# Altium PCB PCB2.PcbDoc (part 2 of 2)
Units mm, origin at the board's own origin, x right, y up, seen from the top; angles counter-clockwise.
Board outline 165.1 x 160.02 mm, 2 copper layers (Top Layer, Bottom Layer); 328 components, 756 nets, 2625 pads, 0 vias.
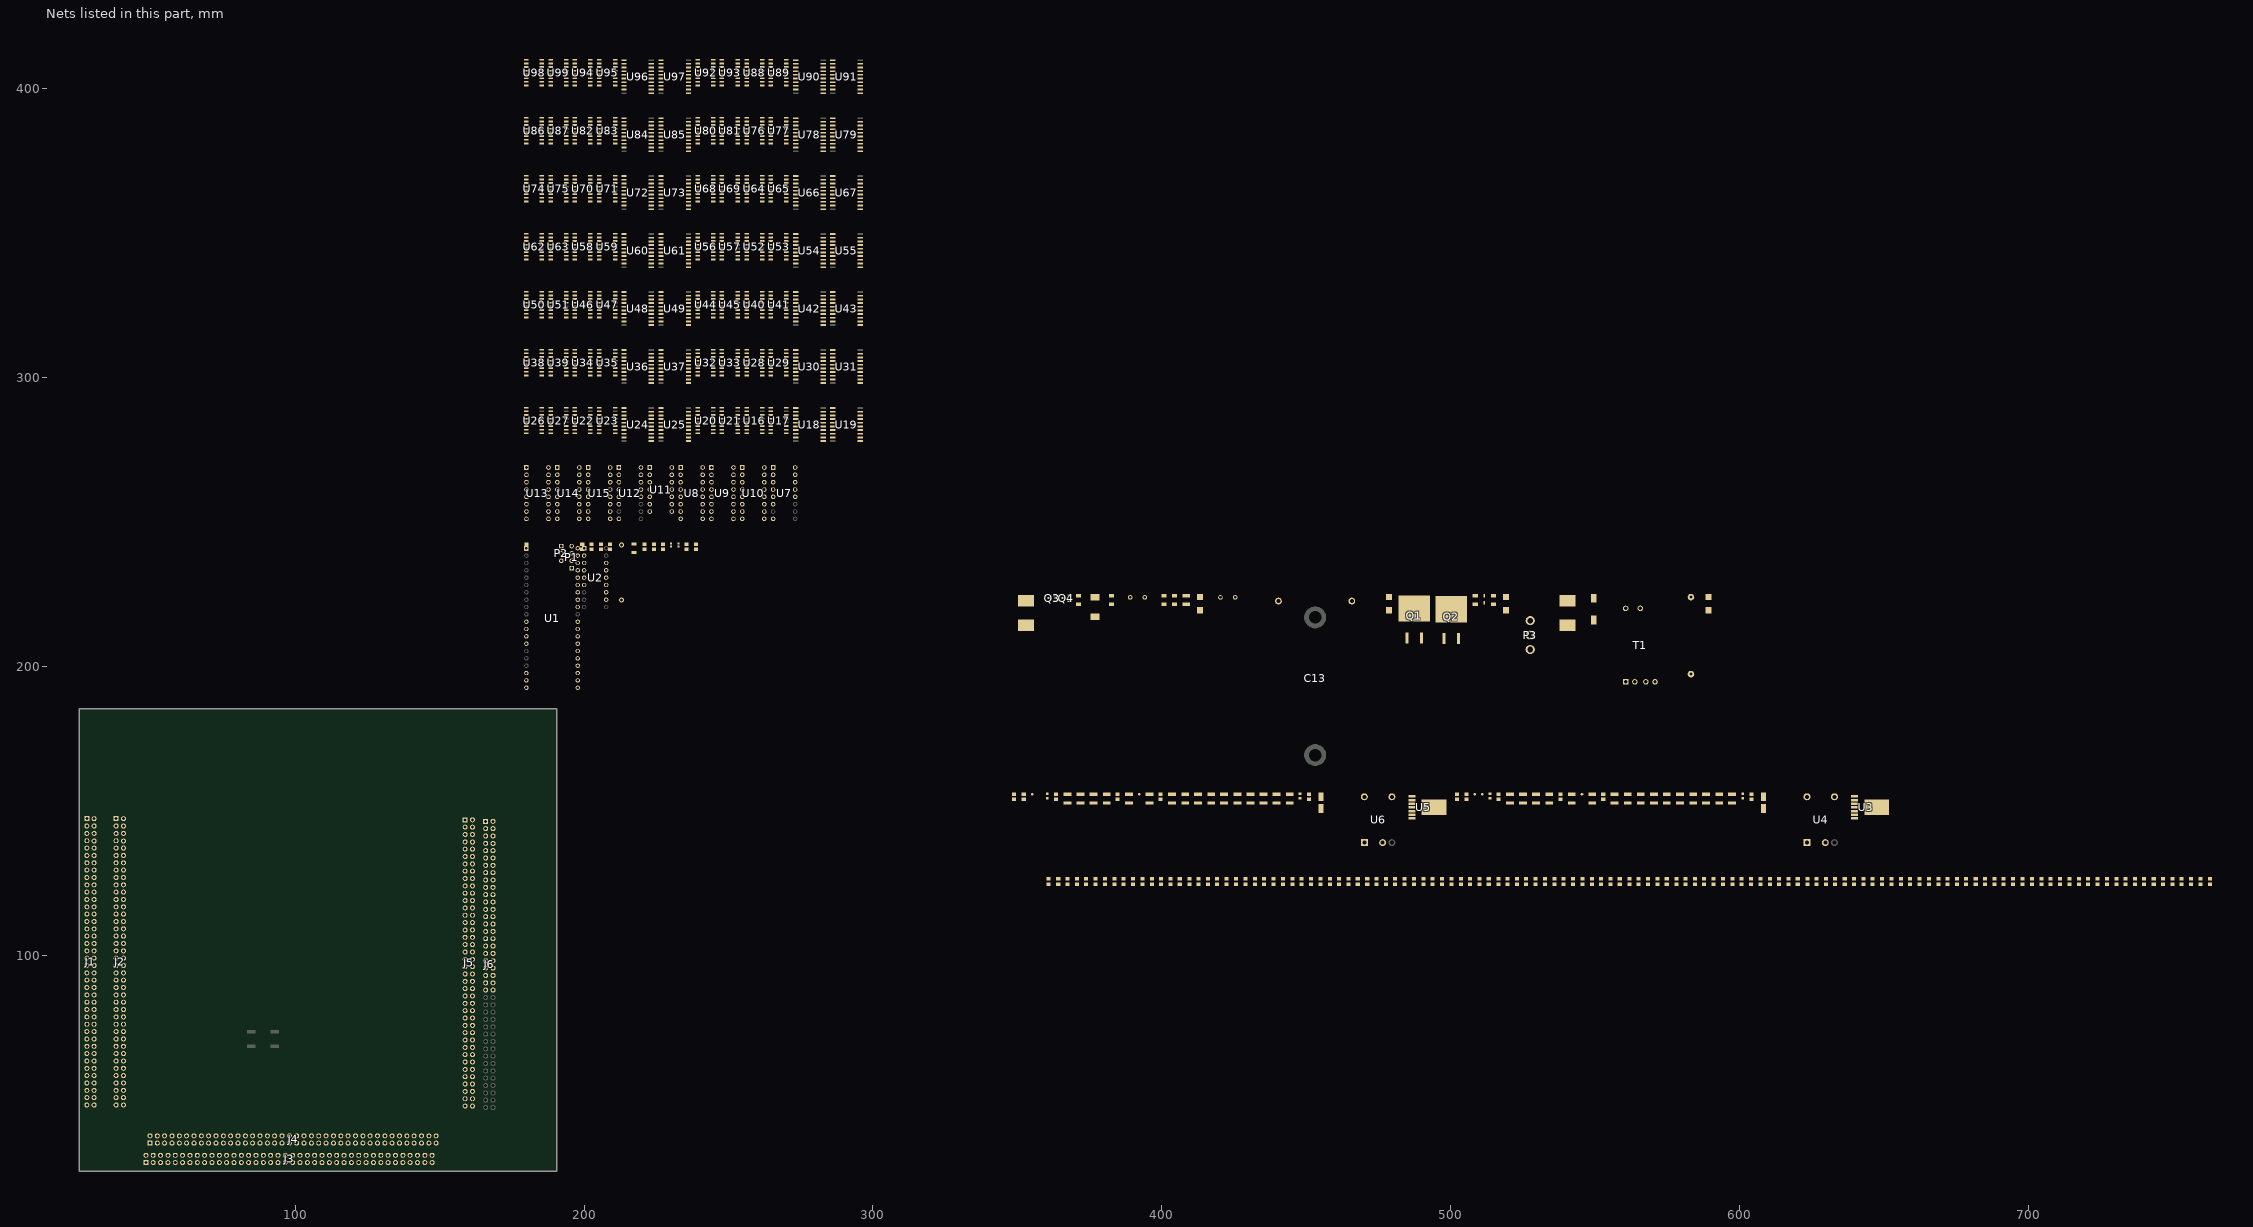
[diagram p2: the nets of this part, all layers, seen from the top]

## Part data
C1 C5 C6 C7 C8 C9 C10 C11 C52 C53 C54 C55 C56 C57 C58 C59 C60 C61 C62 C63 C64 C65 C66 C67 C68 C69 C70 C71 C72 C73 C74 C75 C76 C77 C78 C79 C80 C81 C82 C83 C84 C85 C86 C87 C88 C89 C90 C91 C92 C93 C94 C95 C96 C97 C98 C99 C100 C101 C102 C103 C104 C105 C106 C107 C108 C109 C110 C111 C112 C113 C114 C115 C116 C117 C118 C119 C120 C121 C122 C123 C124 C125 C126 C127 C128 C129 C130 C131 C132 C133 C134 C135 C136 C137 C138 C139 C140 C141 C142 C143 C144 C145 C146 C147 C148 C149 C150 C151 C152 C153 C154 C155 C156 C157 C158 C159 C160 C161 C162 C163 C164 C165 C166 C167 C168 C169 C170 C171 C172 C173 C174 C175 C176: "CAPACITOR, CERAMIC, 0.1UF, 10%, X7R, 50V, 0805"
C2 C3: "CAP CERAMIC 22PF 25V 10% COG 0402"
C4: "CAPACITOR, CERAMIC, 0.47UF 10%, X7R, 50V, 0805"
C12 C15: "CAPACITOR, ALUM ELECT, 470UF, 50V, 477-50V-20AV, -55C TO 105 C"
C13: library part MLPCAPSHORT.1
C14: "CAPACITOR, CERAMIC, 1.0UF 10%, X7R, 100V, 2.7mm"
C16 C17 C18 C19 C27 C28 C34 C35 C36 C37 C45 C46: "CAPACITOR, CERAMIC, 4.7UF 10%, X7R, 50V, 1210"
C20 C21 C22 C23 C24 C25 C29 C30 C31 C32 C38 C39 C40 C41 C42 C43 C47 C48 C49 C50: "CAPACITOR, CERAMIC, 22UF 10%, X7R, 25V, 1210"
C26 C44: "CAPACITOR, CERAMIC, 0.033UF 10%, X7R, 50V, 0805"
C33 C51: "CAPACITOR, CERAMIC, 4700PF 10%, X7R, 100V"
CR1: library part 1206_LED_GRN, "LED, GRN, SMT"
CR2 CR3 CR4 CR5: "DIODE, RECTIFIER, 200V, 2 AMP, SMA PACKAGE"
CR6: "DIODE, ZENER, 36V, DO214AB+"
F1: library part FUSE_1A_A, "FUSE, AXIAL LEADED, 1A, 500VAC"
J1 J2 J3 J4 J5 J6: "HEADER, 80 PIN"
L1: "INDUCTOR, BEAD, SMT, 25-300MHz (43 material)"
L2 L3: library part 1489-BF33U_X, "INDUCTOR, PWR, MSS1260"
L4 L5: "INDUCTOR, BEAD, SMT, < 50 MHz (73 material)"
P1: "HEADER, 4 PIN, ST, 0.100 CTRS"
P2: "HEADER, 3 PIN, RA, 0.100 CTRS"
P3: "HEADER, 3 PIN, ST, 5mm CTRS"
Q1: "POWER MOSFET, P-CHANNEL, 100V, 33A, D2PAK"
Q2: "POWER MOSFET, P-CHANNEL, 60V, 27A, D2PAK"
Q3 Q4: library part FMMTA42.1
R1 R11 R17: "RESISTOR, 10K OHM, 1%, 100 PPM, 0805"
R2: "RESISTOR, 56 OHMS, 1%, 20PPM, SILICONE-CERAMIC WIREWOUND"
R3 R6 R7: "RESISTOR, 20K, 1%, 100 PPM, 1206"
R4: "Resistor, General Purpose, 47.5K, 1%, 100 PPM, 1206"
R5: "RESISTOR, THIN FILM 47.5K, 0.1%, 100 PPM, 1206"
R8: "RESISTOR, 10K, 1%, 100 PPM, 1206"
R9 R15: "RESISTOR, 249K OHMS, 1%, 0805"
R10 R16: "RESISTOR, 26.7K OHM, 1%, 100 PPM, 0603"
R12 R18: "RESISTOR, 15K, 1%, 100 PPM, 0805"
R13 R19: "RESISTOR, 1.500K OHM, 5%, 200 PPM, 0603"
R14 R20: "RESISTOR, 1K, 1%, 100 PPM, 0805"
T1: "TRANSFORMER, 400V, 400HZ"
TP14 TP15 TP16 TP22 TP24: library part TP35, "TEST POINT, 0.035 dia Oct pad w/ 0.010 hole, or SMT"
U1: "High Performance, Enhanced Flash, USB Microcontroller with nanoWatt Technology, 32K Flash, 40-Pin PDIP, Industrial Temperature Range"
U2: "3.0V TO 5.5V, Low-Power, up to 1Mbps, True RS-232 Transceiver Using Four 0.1µF External Capacitor"
U3 U5: "3A POWER MODULE, 42V MAX"
U4 U6: "MODULE, 11.85V - 22V SWITCHING REGULATOR (1.5A)"
U7 U8 U9 U10 U12 U13 U14 U15: "3-to-8 Line Decoder Inverting"
U11: "IC, CMOS HEX INVERTER , DIP14"
U16 U17 U20 U21 U22 U23 U26 U27 U28 U29 U32 U33 U34 U35 U38 U39 U40 U41 U44 U45 U46 U47 U50 U51 U52 U53 U56 U57 U58 U59 U62 U63 U64 U65 U68 U69 U70 U71 U74 U75 U76 U77 U80 U81 U82 U83 U86 U87 U88 U89 U92 U93 U94 U95 U98 U99: library part ADG439FBR_X, "IC, 8 channel,  Fault-Protected Analog Multiplexers"
U18 U19 U24 U25 U30 U31 U36 U37 U42 U43 U48 U49 U54 U55 U60 U61 U66 U67 U72 U73 U78 U79 U84 U85 U90 U91 U96 U97: "IC, LATCH, OCTAL TRANSPARENT, TRISTATE"
VR1: library part BZT52CXXX.1

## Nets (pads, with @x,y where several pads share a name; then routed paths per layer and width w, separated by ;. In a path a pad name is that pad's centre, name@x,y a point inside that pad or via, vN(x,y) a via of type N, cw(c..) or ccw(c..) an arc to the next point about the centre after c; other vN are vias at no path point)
28V0: L4.1 L5.1
28VDC: C12.1 L2.2 Q1.4
+5V0: C5.2 C6.2 C8.2 C36.1 C37.1 C38.1 C39.1 C40.1 C44.1 C46.1 C47.1 C48.1 C52.1 C53.1 C54.1 C55.1 C56.1 C57.1 C58.1 C59.1 C60.1 C61.1 C62.1 C63.1 C64.1 C65.1 C66.1 C67.1 C68.1 C69.1 C70.1 C71.1 C72.1 C73.1 C74.1 C75.1 C76.1 C77.1 C78.1 C79.1 C80.1 C81.1 C82.1 C83.1 C84.1 C85.1 C86.1 C87.1 C88.1 C89.1 C90.1 C91.1 C92.1 C93.1 C94.1 C95.1 C96.1 C105.1 C106.1 C107.1 C108.1 C109.1 C110.1 C111.1 C112.1 C137.1 C138.1 C139.1 C140.1 C141.1 C142.1 C143.1 C144.1 C145.1 C146.1 C147.1 C148.1 C149.1 C150.1 C151.1 C152.1 C153.1 C154.1 C155.1 C156.1 C157.1 C158.1 C159.1 C160.1 R1.2 R16.2 U1.11 U1.32 U2.16 U5.7 U6.2 U7.16 U8.16 U9.16 U10.16 U11.14 U12.16 U13.16 U14.16 U15.16 U16.13 U17.4 U20.4 U21.4 U22.4 U23.4 U26.4 U27.4 U28.13 U29.13 U32.13 U33.13 U34.13 U35.13 U38.13 U39.13 U40.13 U41.13 U44.13 U45.13 U46.13 U47.13 U50.13 U51.13 U52.13 U53.13 U56.13 U57.13 U58.13 U59.13 U62.13 U63.13 U64.13 U65.13 U68.13 U69.13 U70.13 U71.13 U74.13 U75.13 U76.13 U77.13 U80.13 U81.13 U82.13 U83.13 U86.13 U87.13 U88.13 U89.13 U92.13 U93.13 U94.13 U95.13 U98.13 U99.13
+5V_USB: P1.1
+15V0: C18.1 C19.1 C20.1 C21.1 C22.1 C26.1 C28.1 C29.1 C30.1 R10.2 U3.7 U4.2
+DCOR: C13.1 Q1.3 Q2.3 R3.2 R4.2
-5V0: C41.1 C42.1 C43.1 C49.1 C50.1 C97.1 C98.1 C99.1 C100.1 C101.1 C102.1 C103.1 C104.1 C113.1 C114.1 C115.1 C116.1 C117.1 C118.1 C119.1 C120.1 C121.1 C122.1 C123.1 C124.1 C125.1 C126.1 C127.1 C128.1 C129.1 C130.1 C131.1 C132.1 C133.1 C134.1 C135.1 C136.1 C161.1 C162.1 C163.1 C164.1 C165.1 C166.1 C167.1 C168.1 C169.1 C170.1 C171.1 C172.1 C173.1 C174.1 C175.1 C176.1 U6.1 U6.5 U17.13 U20.13 U21.13 U22.13 U23.13 U26.13 U27.13 U28.4 U29.4 U32.4 U33.4 U34.4 U35.4 U38.4 U39.4 U40.4 U41.4 U44.4 U45.4 U46.4 U47.4 U50.4 U51.4 U52.4 U53.4 U56.4 U57.4 U58.4 U59.4 U62.4 U63.4 U64.4 U65.4 U68.4 U69.4 U70.4 U71.4 U74.4 U75.4 U76.4 U77.4 U80.4 U81.4 U82.4 U83.4 U86.4 U87.4 U88.4 U89.4 U92.4 U93.4 U94.4 U95.4 U98.4 U99.4
-15V0: C23.1 C24.1 C25.1 C31.1 C32.1 U4.1 U4.5
BJTB1: Q3.1 Q4.3 R4.1
BJTB2: Q4.1 R5.1 R8.2
BJTC1: Q3.3 R6.1
D0: U1.33 U18.3 U19.3 U24.3 U25.3 U30.3 U31.3 U36.3 U37.3 U42.3 U43.3 U48.3 U49.3 U54.3 U55.3 U60.3 U61.3 U66.3 U67.3 U72.3 U73.3 U78.3 U79.3 U84.3 U85.3 U90.3 U91.3 U96.3 U97.3
D1: U1.34 U18.4 U19.4 U24.4 U25.4 U30.4 U31.4 U36.4 U37.4 U42.4 U43.4 U48.4 U49.4 U54.4 U55.4 U60.4 U61.4 U66.4 U67.4 U72.4 U73.4 U78.4 U79.4 U84.4 U85.4 U90.4 U91.4 U96.4 U97.4
D2: U1.35 U18.7 U19.7 U24.7 U25.7 U30.7 U31.7 U36.7 U37.7 U42.7 U43.7 U48.7 U49.7 U54.7 U55.7 U60.7 U61.7 U66.7 U67.7 U72.7 U73.7 U78.7 U79.7 U84.7 U85.7 U90.7 U91.7 U96.7 U97.7
D3: U1.36 U18.8 U19.8 U24.8 U25.8 U30.8 U31.8 U36.8 U37.8 U42.8 U43.8 U48.8 U49.8 U54.8 U55.8 U60.8 U61.8 U66.8 U67.8 U72.8 U73.8 U78.8 U79.8 U84.8 U85.8 U90.8 U91.8 U96.8 U97.8
D4: U1.37 U18.13 U19.13 U24.13 U25.13 U30.13 U31.13 U36.13 U37.13 U42.13 U43.13 U48.13 U49.13 U54.13 U55.13 U60.13 U61.13 U66.13 U67.13 U72.13 U73.13 U78.13 U79.13 U84.13 U85.13 U90.13 U91.13 U96.13 U97.13
D5: U1.38 U18.14 U19.14 U24.14 U25.14 U30.14 U31.14 U36.14 U37.14 U42.14 U43.14 U48.14 U49.14 U54.14 U55.14 U60.14 U61.14 U66.14 U67.14 U72.14 U73.14 U78.14 U79.14 U84.14 U85.14 U90.14 U91.14 U96.14 U97.14
D6: U1.39 U18.17 U19.17 U24.17 U25.17 U30.17 U31.17 U36.17 U37.17 U42.17 U43.17 U48.17 U49.17 U54.17 U55.17 U60.17 U61.17 U66.17 U67.17 U72.17 U73.17 U78.17 U79.17 U84.17 U85.17 U90.17 U91.17 U96.17 U97.17
D7: U1.40 U18.18 U19.18 U24.18 U25.18 U30.18 U31.18 U36.18 U37.18 U42.18 U43.18 U48.18 U49.18 U54.18 U55.18 U60.18 U61.18 U66.18 U67.18 U72.18 U73.18 U78.18 U79.18 U84.18 U85.18 U90.18 U91.18 U96.18 U97.18
D+: P1.2 U1.24
D-: P1.3 U1.23
DGND: C12.2 C13.2 C16.2 C17.2 C18.2 C19.2 C20.2 C21.2 C22.2 C23.2 C24.2 C25.2 C27.2 C28.2 C29.2 C30.2 C31.2 C32.2 C33.2 C34.2 C35.2 C36.2 C37.2 C38.2 C39.2 C40.2 C41.2 C42.2 C43.2 C45.2 C46.2 C47.2 C48.2 C49.2 C50.2 C51.2 L3.2 Q3.2 Q4.2 R7.1 R8.1 R12.1 R13.1 R14.1 R18.1 R19.1 R20.1 U3.4 U3.8 U5.4 U5.8
DLE1: U1.27 U7.4 U9.4 U10.4 U11.1 U12.6 U13.6 U14.6 U15.6
DLE2: U1.28 U7.6 U8.4 U9.5 U10.6 U11.9 U11.11 U13.4 U14.4
DLE3: U1.29 U8.5 U9.6 U10.5 U11.3 U11.5 U11.13 U13.5 U15.5
GND: C1.1 C2.1 C3.1 C4.1 C5.1 C6.1 C8.1 C9.1 C11.1 C52.2 C53.2 C54.2 C55.2 C56.2 C57.2 C58.2 C59.2 C60.2 C61.2 C62.2 C63.2 C64.2 C65.2 C66.2 C67.2 C68.2 C69.2 C70.2 C71.2 C72.2 C73.2 C74.2 C75.2 C76.2 C77.2 C78.2 C79.2 C80.2 C81.2 C82.2 C83.2 C84.2 C85.2 C86.2 C87.2 C88.2 C89.2 C90.2 C91.2 C92.2 C93.2 C94.2 C95.2 C96.2 C97.2 C98.2 C99.2 C100.2 C101.2 C102.2 C103.2 C104.2 C105.2 C106.2 C107.2 C108.2 C109.2 C110.2 C111.2 C112.2 C113.2 C114.2 C115.2 C116.2 C117.2 C118.2 C119.2 C120.2 C121.2 C122.2 C123.2 C124.2 C125.2 C126.2 C127.2 C128.2 C129.2 C130.2 C131.2 C132.2 C133.2 C134.2 C135.2 C136.2 C137.2 C138.2 C139.2 C140.2 C141.2 C142.2 C143.2 C144.2 C145.2 C146.2 C147.2 C148.2 C149.2 C150.2 C151.2 C152.2 C153.2 C154.2 C155.2 C156.2 C157.2 C158.2 C159.2 C160.2 C161.2 C162.2 C163.2 C164.2 C165.2 C166.2 C167.2 C168.2 C169.2 C170.2 C171.2 C172.2 C173.2 C174.2 C175.2 C176.2 P1.4 P2.1 P3.3 R2.1 U1.12 U1.31 U2.15 U7.8 U8.8 U9.8 U10.8 U11.7 U12.8 U13.8 U14.8 U15.8 U16.5 U17.5 U20.5 U21.5 U22.5 U23.5 U26.5 U27.5 U28.5 U29.5 U32.5 U33.5 U34.5 U35.5 U38.5 U39.5 U40.5 U41.5 U44.5 U45.5 U46.5 U47.5 U50.5 U51.5 U52.5 U53.5 U56.5 U57.5 U58.5 U59.5 U62.5 U63.5 U64.5 U65.5 U68.5 U69.5 U70.5 U71.5 U74.5 U75.5 U76.5 U77.5 U80.5 U81.5 U82.5 U83.5 U86.5 U87.5 U88.5 U89.5 U92.5 U93.5 U94.5 U95.5 U98.5 U99.5
LE1: U8.15 U18.11
LE2: U8.14 U24.11
LE3: U8.13 U19.11
LE4: U8.12 U25.11
LE5: U8.11 U30.11
LE6: U8.10 U36.11
LE7: U8.9 U31.11
LE8: U8.7 U37.11
LE9: U9.15 U42.11
LE10: U9.14 U48.11
LE11: U9.13 U43.11
LE12: U9.12 U49.11
LE13: U9.11 U54.11
LE14: U9.10 U60.11
LE15: U9.9 U55.11
LE16: U9.7 U61.11
LE17: U10.15 U66.11
LE18: U10.14 U72.11
LE19: U10.13 U67.11
LE20: U10.12 U73.11
LE21: U10.11 U78.11
LE22: U10.10 U84.11
LE23: U10.9 U79.11
LE24: U10.7 U85.11
LE25: U7.15 U90.11
LE26: U7.14 U96.11
LE27: U7.13 U91.11
LE28: U7.12 U97.11
LOE1: U13.15 U18.1
LOE2: U13.14 U24.1
LOE3: U13.13 U19.1
LOE4: U13.12 U25.1
LOE5: U13.11 U30.1
LOE6: U13.10 U36.1
LOE7: U13.9 U31.1
LOE8: U13.7 U37.1
LOE9: U14.15 U42.1
LOE10: U14.14 U48.1
LOE11: U14.13 U43.1
LOE12: U14.12 U49.1
LOE13: U14.11 U54.1
LOE14: U14.10 U60.1
LOE15: U14.9 U55.1
LOE16: U14.7 U61.1
LOE17: U15.15 U66.1
LOE18: U15.14 U72.1
LOE19: U15.13 U67.1
LOE20: U15.12 U73.1
LOE21: U15.11 U78.1
LOE22: U15.10 U84.1
LOE23: U15.9 U79.1
LOE24: U15.7 U85.1
LOE25: U12.15 U90.1
LOE26: U12.14 U96.1
LOE27: U12.13 U91.1
LOE28: U12.12 U97.1
MOSFEED1: Q2.1 R3.1 R6.2
NetC1_2: C1.2 R1.1 U1.1
NetC2_2: C2.2 U1.13
NetC3_2: C3.2 U1.14
NetC4_2: C4.2 U1.18
NetC7_1: C7.1 U2.3
NetC7_2: C7.2 U2.1
NetC9_2: C9.2 U2.2
NetC10_1: C10.1 U2.5
NetC10_2: C10.2 U2.4
NetC11_2: C11.2 U2.6
NetC14_1: C14.1 C15.1 CR3.1 CR4.1 CR6.1 L2.1
NetC14_2: C14.2 C15.2 CR2.2 CR5.2 CR6.2 L3.1
NetC16_1: C16.1 C17.1 C27.1 L4.2 R9.1 R11.2 U3.1
NetC26_2: C26.2 R10.1 R13.2 TP14.1 U3.6
NetC33_1: C33.1 TP16.1 U3.5
NetC34_1: C34.1 C35.1 C45.1 L5.2 R15.1 R17.2 U5.1
NetC44_2: C44.2 R16.1 R19.2 TP22.1 U5.6
NetC51_1: C51.1 TP24.1 U5.5
NetCR1_1: CR1.1 R2.2
NetCR1_2: CR1.2 U1.19
NetCR2_1: CR2.1 CR3.2 T1.5
NetCR4_2: CR4.2 CR5.1 T1.6
NetF1_1: F1.1 P3.1
NetF1_2: F1.2 L1.1
NetL1_2: L1.2 T1.1
NetP3_2: P3.2 T1.4
NetQ1_1: Q1.1 R7.2
NetR9_2: R9.2 U3.2
NetR11_1: R11.1 R14.2 TP15.1 U3.3
NetR12_2: R12.2 U4.4
NetR15_2: R15.2 U5.2
NetR17_1: R17.1 R20.2 U5.3
NetR18_2: R18.2 U6.4
NetT1_2: T1.2 T1.3
NetU7_5: U7.5 U11.4
NetU8_6: U8.6 U11.2
NetU11_6: U11.6 U14.5
NetU11_8: U11.8 U12.4
NetU11_10: U11.10 U15.4
NetU11_12: U11.12 U12.5
NetU16_1: U16.1 U18.2
NetU16_8: U16.8 U18.5
NetU16_9: U16.9 U18.6
NetU16_16: U16.16 U18.9
NetU17_1: U17.1 U19.2
NetU17_8: U17.8 U19.5
NetU17_9: U17.9 U19.6
NetU17_16: U17.16 U19.9
NetU18_12: U18.12 U20.1
NetU18_15: U18.15 U20.8
NetU18_16: U18.16 U20.9
NetU18_19: U18.19 U20.16
NetU19_12: U19.12 U21.1
NetU19_15: U19.15 U21.8
NetU19_16: U19.16 U21.9
NetU19_19: U19.19 U21.16
NetU22_1: U22.1 U24.2
NetU22_8: U22.8 U24.5
NetU22_9: U22.9 U24.6
NetU22_16: U22.16 U24.9
NetU23_1: U23.1 U25.2
NetU23_8: U23.8 U25.5
NetU23_9: U23.9 U25.6
NetU23_16: U23.16 U25.9
NetU24_12: U24.12 U26.1
NetU24_15: U24.15 U26.8
NetU24_16: U24.16 U26.9
NetU24_19: U24.19 U26.16
NetU25_12: U25.12 U27.1
NetU25_15: U25.15 U27.8
NetU25_16: U25.16 U27.9
NetU25_19: U25.19 U27.16
NetU28_1: U28.1 U30.2
NetU28_8: U28.8 U30.9
NetU28_9: U28.9 U30.6
NetU28_16: U28.16 U30.5
NetU29_1: U29.1 U31.2
NetU29_8: U29.8 U31.9
NetU29_9: U29.9 U31.6
NetU29_16: U29.16 U31.5
NetU30_12: U30.12 U32.1
NetU30_15: U30.15 U32.16
NetU30_16: U30.16 U32.9
NetU30_19: U30.19 U32.8
NetU31_12: U31.12 U33.1
NetU31_15: U31.15 U33.16
NetU31_16: U31.16 U33.9
NetU31_19: U31.19 U33.8
NetU34_1: U34.1 U36.2
NetU34_8: U34.8 U36.9
NetU34_9: U34.9 U36.6
NetU34_16: U34.16 U36.5
NetU35_1: U35.1 U37.2
NetU35_8: U35.8 U37.9
NetU35_9: U35.9 U37.6
NetU35_16: U35.16 U37.5
NetU36_12: U36.12 U38.1
NetU36_15: U36.15 U38.16
NetU36_16: U36.16 U38.9
NetU36_19: U36.19 U38.8
NetU37_12: U37.12 U39.1
NetU37_15: U37.15 U39.16
NetU37_16: U37.16 U39.9
NetU37_19: U37.19 U39.8
NetU40_1: U40.1 U42.2
NetU40_8: U40.8 U42.9
NetU40_9: U40.9 U42.6
NetU40_16: U40.16 U42.5
NetU41_1: U41.1 U43.2
NetU41_8: U41.8 U43.9
NetU41_9: U41.9 U43.6
NetU41_16: U41.16 U43.5
NetU42_12: U42.12 U44.1
NetU42_15: U42.15 U44.16
NetU42_16: U42.16 U44.9
NetU42_19: U42.19 U44.8
NetU43_12: U43.12 U45.1
NetU43_15: U43.15 U45.16
NetU43_16: U43.16 U45.9
NetU43_19: U43.19 U45.8
NetU46_1: U46.1 U48.2
NetU46_8: U46.8 U48.9
NetU46_9: U46.9 U48.6
NetU46_16: U46.16 U48.5
NetU47_1: U47.1 U49.2
NetU47_8: U47.8 U49.9
NetU47_9: U47.9 U49.6
NetU47_16: U47.16 U49.5
NetU48_12: U48.12 U50.1
NetU48_15: U48.15 U50.16
NetU48_16: U48.16 U50.9
NetU48_19: U48.19 U50.8
NetU49_12: U49.12 U51.1
NetU49_15: U49.15 U51.16
NetU49_16: U49.16 U51.9
NetU49_19: U49.19 U51.8
NetU52_1: U52.1 U54.2
NetU52_8: U52.8 U54.9
NetU52_9: U52.9 U54.6
NetU52_16: U52.16 U54.5
NetU53_1: U53.1 U55.2
NetU53_8: U53.8 U55.9
NetU53_9: U53.9 U55.6
NetU53_16: U53.16 U55.5
NetU54_12: U54.12 U56.1
NetU54_15: U54.15 U56.16
NetU54_16: U54.16 U56.9
NetU54_19: U54.19 U56.8
NetU55_12: U55.12 U57.1
NetU55_15: U55.15 U57.16
NetU55_16: U55.16 U57.9
NetU55_19: U55.19 U57.8
NetU58_1: U58.1 U60.2
NetU58_8: U58.8 U60.9
NetU58_9: U58.9 U60.6
NetU58_16: U58.16 U60.5
NetU59_1: U59.1 U61.2
NetU59_8: U59.8 U61.9
NetU59_9: U59.9 U61.6
NetU59_16: U59.16 U61.5
NetU60_12: U60.12 U62.1
NetU60_15: U60.15 U62.16
NetU60_16: U60.16 U62.9
NetU60_19: U60.19 U62.8
NetU61_12: U61.12 U63.1
NetU61_15: U61.15 U63.16
NetU61_16: U61.16 U63.9
NetU61_19: U61.19 U63.8
NetU64_1: U64.1 U66.2
NetU64_8: U64.8 U66.9
NetU64_9: U64.9 U66.6
NetU64_16: U64.16 U66.5
NetU65_1: U65.1 U67.2
NetU65_8: U65.8 U67.9
NetU65_9: U65.9 U67.6
NetU65_16: U65.16 U67.5
NetU66_12: U66.12 U68.1
NetU66_15: U66.15 U68.16
NetU66_16: U66.16 U68.9
NetU66_19: U66.19 U68.8
NetU67_12: U67.12 U69.1
NetU67_15: U67.15 U69.16
NetU67_16: U67.16 U69.9
NetU67_19: U67.19 U69.8
NetU70_1: U70.1 U72.2
NetU70_8: U70.8 U72.9
NetU70_9: U70.9 U72.6
NetU70_16: U70.16 U72.5
NetU71_1: U71.1 U73.2
NetU71_8: U71.8 U73.9
NetU71_9: U71.9 U73.6
NetU71_16: U71.16 U73.5
NetU72_12: U72.12 U74.1
NetU72_15: U72.15 U74.16
NetU72_16: U72.16 U74.9
NetU72_19: U72.19 U74.8
NetU73_12: U73.12 U75.1
NetU73_15: U73.15 U75.16
NetU73_16: U73.16 U75.9
NetU73_19: U73.19 U75.8
NetU76_1: U76.1 U78.2
NetU76_8: U76.8 U78.9
NetU76_9: U76.9 U78.6
NetU76_16: U76.16 U78.5
NetU77_1: U77.1 U79.2
NetU77_8: U77.8 U79.9
NetU77_9: U77.9 U79.6
NetU77_16: U77.16 U79.5
NetU78_12: U78.12 U80.1
NetU78_15: U78.15 U80.16
NetU78_16: U78.16 U80.9
NetU78_19: U78.19 U80.8
NetU79_12: U79.12 U81.1
NetU79_15: U79.15 U81.16
NetU79_16: U79.16 U81.9
NetU79_19: U79.19 U81.8
NetU82_1: U82.1 U84.2
NetU82_8: U82.8 U84.9
NetU82_9: U82.9 U84.6
NetU82_16: U82.16 U84.5
NetU83_1: U83.1 U85.2
NetU83_8: U83.8 U85.9
NetU83_9: U83.9 U85.6
NetU83_16: U83.16 U85.5
NetU84_12: U84.12 U86.1
NetU84_15: U84.15 U86.16
NetU84_16: U84.16 U86.9
NetU84_19: U84.19 U86.8
NetU85_12: U85.12 U87.1
NetU85_15: U85.15 U87.16
NetU85_16: U85.16 U87.9
NetU85_19: U85.19 U87.8
NetU88_1: U88.1 U90.2
NetU88_8: U88.8 U90.9
NetU88_9: U88.9 U90.6
NetU88_16: U88.16 U90.5
NetU89_1: U89.1 U91.2
NetU89_8: U89.8 U91.9
NetU89_9: U89.9 U91.6
NetU89_16: U89.16 U91.5
NetU90_12: U90.12 U92.1
NetU90_15: U90.15 U92.16
NetU90_16: U90.16 U92.9
NetU90_19: U90.19 U92.8
NetU91_12: U91.12 U93.1
NetU91_15: U91.15 U93.16
NetU91_16: U91.16 U93.9
NetU91_19: U91.19 U93.8
NetU94_1: U94.1 U96.2
NetU94_8: U94.8 U96.9
NetU94_9: U94.9 U96.6
NetU94_16: U94.16 U96.5
NetU95_1: U95.1 U97.2
NetU95_8: U95.8 U97.9
NetU95_9: U95.9 U97.6
NetU95_16: U95.16 U97.5
NetU96_12: U96.12 U98.1
NetU96_15: U96.15 U98.16
NetU96_16: U96.16 U98.9
NetU96_19: U96.19 U98.8
NetU97_12: U97.12 U99.1
NetU97_15: U97.15 U99.16
NetU97_16: U97.16 U99.9
NetU97_19: U97.19 U99.8
RXD: U1.26 U2.12
RXOUT: P2.3 U2.13
S1I: J1.1 U16.3
S1O: J1.17 U16.2
S2I: J1.2 U16.6
S2O: J1.18 U16.7
S3I: J1.3 U16.11
S3O: J1.19 U16.10
S4I: J1.4 U16.14
S4O: J1.20
S5I: J1.5 U20.3
S5O: J1.21 U20.2
S6I: J1.6 U20.6
S6O: J1.22 U20.7
S7I: J1.7 U20.11
S7O: J1.23 U20.10
S8I: J1.8 U20.14
S8O: J1.24
S9I: J1.9 U22.3
S9O: J1.25 U22.2
S10I: J1.10 U22.6
S10O: J1.26 U22.7
S11I: J1.11 U22.11
S11O: J1.27 U22.10
S12I: J1.12 U22.14
S12O: J1.28
S13I: J1.13 U26.3
S13O: J1.29 U26.2
S14I: J1.14 U26.6
S14O: J1.30 U26.7
S15I: J1.15 U26.11
S15O: J1.31 U26.10
S16I: J1.16 U26.14
S16O: J1.32
S17I: J1.33 U28.3
S17O: J2.6 U28.2
S18I: J1.34 U28.14
S18O: J2.7 U28.15
S19I: J1.35 U28.11
S19O: J2.8 U28.10
S20I: J1.36 U28.6
S20O: J2.9 U28.7
S21I: J1.37 U32.3
S21O: J2.10 U32.2
S22I: J1.75 U32.14
S22O: J2.11 U32.15
S23I: J1.76 U32.11
S23O: J2.12 U32.10
S24I: J1.77 U32.6
S24O: J2.13 U32.7
S25I: J1.78 U34.3
S25O: J2.14 U34.2
S26I: J1.79 U34.14
S26O: J2.15 U34.15
S27I: J1.80 U34.11
S27O: J2.16 U34.10
S28I: J2.1 U34.6
S28O: J2.17 U34.7
S29I: J2.2 U38.3
S29O: J2.18 U38.2
S30I: J2.3 U38.14
S30O: J2.19 U38.15
S31I: J2.4 U38.11
S31O: J2.20 U38.10
S32I: J2.5 U38.6
S32O: J2.21 U38.7
S33I: J2.22 U29.3
S33O: J2.75 U29.2
S34I: J2.23 U29.14
S34O: J2.76 U29.15
S35I: J2.24 U29.11
S35O: J2.77 U29.10
S36I: J2.25 U29.6
S36O: J2.78 U29.7
S37I: J2.26 U33.3
S37O: J2.79 U33.2
S38I: J2.27 U33.14
S38O: J2.80 U33.15
S39I: J2.28 U33.11
S39O: J3.1 U33.10
S40I: J2.29 U33.6
S40O: J3.2 U33.7
S41I: J2.30 U35.3
S41O: J3.3 U35.2
S42I: J2.31 U35.14
S42O: J3.4 U35.15
S43I: J2.69 U35.11
S43O: J3.5 U35.10
S44I: J2.70 U35.6
S44O: J3.6 U35.7
S45I: J2.71 U39.3
S45O: J3.7 U39.2
S46I: J2.72 U39.14
S46O: J3.8 U39.15
S47I: J2.73 U39.11
S47O: J3.9 U39.10
S48I: J2.74 U39.6
S48O: J3.10 U39.7
S49I: J3.11 U40.3
S49O: J3.64 U40.2
S50I: J3.12 U40.14
S50O: J3.65 U40.15
S51I: J3.13 U40.11
S51O: J3.66 U40.10
S52I: J3.14 U40.6
S52O: J3.67 U40.7
S53I: J3.15 U44.3
S53O: J3.68 U44.2
S54I: J3.16 U44.14
S54O: J3.69 U44.15
S55I: J3.17 U44.11
S55O: J3.70 U44.10
S56I: J3.18 U44.6
S56O: J3.71 U44.7
S57I: J3.19 U46.3
S57O: J3.72 U46.2
S58I: J3.20 U46.14
S58O: J3.73 U46.15
S59I: J3.21 U46.11
S59O: J3.74 U46.10
S60I: J3.22 U46.6
S60O: J3.75 U46.7
S61I: J3.23 U50.3
S61O: J3.76 U50.2
S62I: J3.24 U50.14
S62O: J3.77 U50.15
S63I: J3.25 U50.11
S63O: J3.78 U50.10
S64I: J3.63 U50.6
S64O: J3.79 U50.7
S65I: J3.80 U41.3
S65O: J4.16 U41.2
S66I: J4.1 U41.14
S66O: J4.17 U41.15
S67I: J4.2 U41.11
S67O: J4.18 U41.10
S68I: J4.3 U41.6
S68O: J4.19 U41.7
S69I: J4.4 U45.3
S69O: J4.57 U45.2
S70I: J4.5 U45.14
S70O: J4.58 U45.15
S71I: J4.6 U45.11
S71O: J4.59 U45.10
S72I: J4.7 U45.6
S72O: J4.60 U45.7
S73I: J4.8 U47.3
S73O: J4.61 U47.2
S74I: J4.9 U47.14
S74O: J4.62 U47.15
S75I: J4.10 U47.11
S75O: J4.63 U47.10
S76I: J4.11 U47.6
S76O: J4.64 U47.7
S77I: J4.12 U51.3
S77O: J4.65 U51.2
S78I: J4.13 U51.14
S78O: J4.66 U51.15
S79I: J4.14 U51.11
S79O: J4.67 U51.10
S80I: J4.15 U51.6
S80O: J4.68 U51.7
S81I: J4.69 J5.5 U52.2 U52.3
S82I: J4.70 J5.6 U52.14 U52.15
S83I: J4.71 J5.7 U52.10 U52.11
S84I: J4.72 J5.8 U52.6 U52.7
S85I: J4.73 J5.9 U56.2 U56.3
S86I: J4.74 J5.10 U56.14 U56.15
S87I: J4.75 J5.11 U56.10 U56.11
S88I: J4.76 J5.12 U56.6 U56.7
S89I: J4.77 J5.13 U58.2 U58.3
S90I: J4.78 J5.51 U58.14 U58.15
S91I: J4.79 J5.52 U58.10 U58.11
S92I: J4.80 J5.53 U58.6 U58.7
S93I: J5.1 J5.54 U62.2 U62.3
S94I: J5.2 J5.55 U62.14 U62.15
S95I: J5.3 J5.56 U62.10 U62.11
S96I: J5.4 J5.57 U62.6 U62.7
S97I: J5.58 J5.74 U53.2 U53.3
S98I: J5.59 J5.75 U53.14 U53.15
S99I: J5.60 J5.76 U53.10 U53.11
S100I: J5.61 J5.77 U53.6 U53.7
S101I: J5.62 J5.78 U57.2 U57.3
S102I: J5.63 J5.79 U57.14 U57.15
S103I: J5.64 J5.80 U57.10 U57.11
S104I: J5.65 J6.1 U57.6 U57.7
S105I: J5.66 J6.2 U59.2 U59.3
S106I: J5.67 J6.3 U59.14 U59.15
S107I: J5.68 J6.4 U59.10 U59.11
S108I: J5.69 J6.5 U59.6 U59.7
S109I: J5.70 J6.6 U63.2 U63.3
S110I: J5.71 J6.7 U63.14 U63.15
S111I: J1.38 J5.72 U63.10 U63.11
S112I: J1.39 J5.73 U63.6 U63.7
S113I: J1.40 U64.3
S113O: J1.56 U64.2
S114I: J1.41 U64.14
S114O: J1.57 U64.15
S115I: J1.42 U64.11
S115O: J1.58 U64.10
S116I: J1.43 U64.6
S116O: J1.59 U64.7
S117I: J1.44 U68.3
S117O: J1.60 U68.2
S118I: J1.45 U68.14
S118O: J1.61 U68.15
S119I: J1.46 U68.11
S119O: J1.62 U68.10
S120I: J1.47 U68.6
S120O: J1.63 U68.7
S121I: J1.48 U70.3
S121O: J1.64 U70.2
S122I: J1.49 U70.14
S122O: J1.65 U70.15
S123I: J1.50 U70.11
S123O: J1.66 U70.10
S124I: J1.51 U70.6
S124O: J1.67 U70.7
S125I: J1.52 U74.3
S125O: J1.68 U74.2
S126I: J1.53 U74.14
S126O: J1.69 U74.15
S127I: J1.54 U74.11
S127O: J1.70 U74.10
S128I: J1.55 U74.6
S128O: J1.71 U74.7
S129I: J1.72 J2.45 U65.2 U65.3
S130I: J1.73 J2.46 U65.14 U65.15
S131I: J1.74 J2.47 U65.10 U65.11
S132I: J2.32 J2.48 U65.6 U65.7
S133I: J2.33 J2.49 U69.2 U69.3
S134I: J2.34 J2.50 U69.14 U69.15
S135I: J2.35 J2.51 U69.10 U69.11
S136I: J2.36 J2.52 U69.6 U69.7
S137I: J2.37 J2.53 U71.2 U71.3
S138I: J2.38 J2.54 U71.14 U71.15
S139I: J2.39 J2.55 U71.10 U71.11
S140I: J2.40 J2.56 U71.6 U71.7
S141I: J2.41 J2.57 U75.2 U75.3
S142I: J2.42 J2.58 U75.14 U75.15
S143I: J2.43 J2.59 U75.10 U75.11
S144I: J2.44 J2.60 U75.6 U75.7
S145I: J2.61 U76.3
S145O: J3.34 U76.2
S146I: J2.62 U76.14
S146O: J3.35 U76.15
S147I: J2.63 U76.11
S147O: J3.36 U76.10
S148I: J2.64 U76.6
S148O: J3.37 U76.7
S149I: J2.65 U80.3
S149O: J3.38 U80.2
S150I: J2.66 U80.14
S150O: J3.39 U80.15
S151I: J2.67 U80.11
S151O: J3.40 U80.10
S152I: J2.68 U80.6
S152O: J3.41 U80.7
S153I: J3.26 U82.3
S153O: J3.42 U82.2
S154I: J3.27 U82.14
S154O: J3.43 U82.15
S155I: J3.28 U82.11
S155O: J3.44 U82.10
S156I: J3.29 U82.6
S156O: J3.45 U82.7
S157I: J3.30 U86.3
S157O: J3.46 U86.2
S158I: J3.31 U86.14
S158O: J3.47 U86.15
S159I: J3.32 U86.11
S159O: J3.48 U86.10
S160I: J3.33 U86.6
S160O: J3.49 U86.7
S161I: J3.50 U77.3
S161O: J4.23 U77.2
S162I: J3.51 U77.14
S162O: J4.24 U77.15
S163I: J3.52 U77.11
S163O: J4.25 U77.10
S164I: J3.53 U77.6
S164O: J4.26 U77.7
S165I: J3.54 U81.3
S165O: J4.27 U81.2
S166I: J3.55 U81.14
S166O: J4.28 U81.15
S167I: J3.56 U81.11
S167O: J4.29 U81.10
S168I: J3.57 U81.6
S168O: J4.30 U81.7
S169I: J3.58 U83.3
S169O: J4.31 U83.2
S170I: J3.59 U83.14
S170O: J4.32 U83.15
S171I: J3.60 U83.11
S171O: J4.33 U83.10
S172I: J3.61 U83.6
S172O: J4.34 U83.7
S173I: J3.62 U87.3
S173O: J4.35 U87.2
S174I: J4.20 U87.14
S174O: J4.36 U87.15
S175I: J4.21 U87.11
S175O: J4.37 U87.10
S176I: J4.22 U87.6
S176O: J4.38 U87.7
S177I: J4.39 U88.3
S177O: J4.55 U88.2
S178I: J4.40 U88.14
S178O: J4.56 U88.15
S179I: J4.41 U88.11
S179O: J5.14 U88.10
S180I: J4.42 U88.6
S180O: J5.15 U88.7
S181I: J4.43 U92.3
S181O: J5.16 U92.2
S182I: J4.44 U92.14
S182O: J5.17 U92.15
S183I: J4.45 U92.11
S183O: J5.18 U92.10
S184I: J4.46 U92.6
S184O: J5.19 U92.7
S185I: J4.47 U94.3
S185O: J5.20 U94.2
S186I: J4.48 U94.14
S186O: J5.21 U94.15
S187I: J4.49 U94.11
S187O: J5.22 U94.10
S188I: J4.50 U94.6
S188O: J5.23 U94.7
S189I: J4.51 U98.3
S189O: J5.24 U98.2
S190I: J4.52 U98.14
S190O: J5.25 U98.15
S191I: J4.53 U98.11
S191O: J5.26 U98.10
S192I: J4.54 U98.6
S192O: J5.27 U98.7
S193I: J5.28 U89.3
S193O: J5.44 U89.2
S194I: J5.29 U89.14
S194O: J5.45 U89.15
S195I: J5.30 U89.11
S195O: J5.46 U89.10
S196I: J5.31 U89.6
S196O: J5.47 U89.7
S197I: J5.32 U93.3
S197O: J5.48 U93.2
S198I: J5.33 U93.14
S198O: J5.49 U93.15
S199I: J5.34 U93.11
S199O: J5.50 U93.10
S200I: J5.35 U93.6
S200O: J6.8 U93.7
S201I: J5.36 U95.3
S201O: J6.9 U95.2
S202I: J5.37 U95.14
S202O: J6.10 U95.15
S203I: J5.38 U95.11
S203O: J6.11 U95.10
S204I: J5.39 U95.6
S204O: J6.12 U95.7
S205I: J5.40 U99.3
S205O: J6.13 U99.2
S206I: J5.41 U99.14
S206O: J6.14 U99.15
S207I: J5.42 U99.11
S207O: J6.15 U99.10
S208I: J5.43 U99.6
S208O: J6.16 U99.7
S209I: J6.17 U17.3
S209O: J6.33 U17.2
S210I: J6.18 U17.6
S210O: J6.34 U17.7
S211I: J6.19 U17.11
S211O: J6.35 U17.10
S212I: J6.20 U17.14
S212O: J6.36
S213I: J6.21 U21.3
S213O: J6.37 U21.2
S214I: J6.22 U21.6
S214O: J6.38 U21.7
S215I: J6.23 U21.11
S215O: J6.39 U21.10
S216I: J6.24 U21.14
S216O: J6.40
S217I: J6.25 U23.3
S217O: J6.41 U23.2
S218I: J6.26 U23.6
S218O: J6.42 U23.7
S219I: J6.27 U23.11
S219O: J6.43 U23.10
S220I: J6.28 U23.14
S220O: J6.44
S221I: J6.29 U27.3
S221O: J6.45 U27.2
S222I: J6.30 U27.6
S222O: J6.46 U27.7
S223I: J6.31 U27.11
S223O: J6.47 U27.10
S224I: J6.32 U27.14
S224O: J6.48
SLT1: U1.20 U7.1 U8.1 U9.1 U10.1 U12.1 U13.1 U14.1 U15.1
SLT2: U1.21 U7.2 U8.2 U9.2 U10.2 U12.2 U13.2 U14.2 U15.2
SLT3: U1.22 U7.3 U8.3 U9.3 U10.3 U12.3 U13.3 U14.3 U15.3
TXD: U1.25 U2.11
TXOUT: P2.2 U2.14
V28: Q2.4 VR1.1
ZC1: R5.2 VR1.2
pads on no net: BR106.1 BR106.2 BR106.3 BR106.4 C13.3 C13.4 J6.49 J6.50 J6.51 J6.52 J6.53 J6.54 J6.55 J6.56 J6.57 J6.58 J6.59 J6.60 J6.61 J6.62 J6.63 J6.64 J6.65 J6.66 J6.67 J6.68 J6.69 J6.70 J6.71 J6.72 J6.73 J6.74 J6.75 J6.76 J6.77 J6.78 J6.79 J6.80 P3.0 Q1.0 Q2.0 U1.2 U1.3 U1.4 U1.5 U1.6 U1.7 U1.8 U1.9 U1.10 U1.15 U1.16 U1.17 U1.30 U2.7 U2.8 U2.9 U2.10 U2.17 U2.18 U4.3 U6.3 U7.7 U7.9 U7.10 U7.11 U12.7 U12.9 U12.10 U12.11 U16.4 U16.12 U16.15 U17.12 U17.15 U18.10 U18.20 U19.10 U19.20 U20.12 U20.15 U21.12 U21.15 U22.12 U22.15 U23.12 U23.15 U24.10 U24.20 U25.10 U25.20 U26.12 U26.15 U27.12 U27.15 U28.12 U29.12 U30.10 U30.20 U31.10 U31.20 U32.12 U33.12 U34.12 U35.12 U36.10 U36.20 U37.10 U37.20 U38.12 U39.12 U40.12 U41.12 U42.10 U42.20 U43.10 U43.20 U44.12 U45.12 U46.12 U47.12 U48.10 U48.20 U49.10 U49.20 U50.12 U51.12 U52.12 U53.12 U54.10 U54.20 U55.10 U55.20 U56.12 U57.12 U58.12 U59.12 U60.10 U60.20 U61.10 U61.20 U62.12 U63.12 U64.12 U65.12 U66.10 U66.20 U67.10 U67.20 U68.12 U69.12 U70.12 U71.12 U72.10 U72.20 U73.10 U73.20 U74.12 U75.12 U76.12 U77.12 U78.10 U78.20 U79.10 U79.20 U80.12 U81.12 U82.12 U83.12 U84.10 U84.20 U85.10 U85.20 U86.12 U87.12 U88.12 U89.12 U90.10 U90.20 U91.10 U91.20 U92.12 U93.12 U94.12 U95.12 U96.10 U96.20 U97.10 U97.20 U98.12 U99.12

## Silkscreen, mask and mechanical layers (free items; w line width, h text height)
Mechanical 2:
  the board outline again, w0.127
